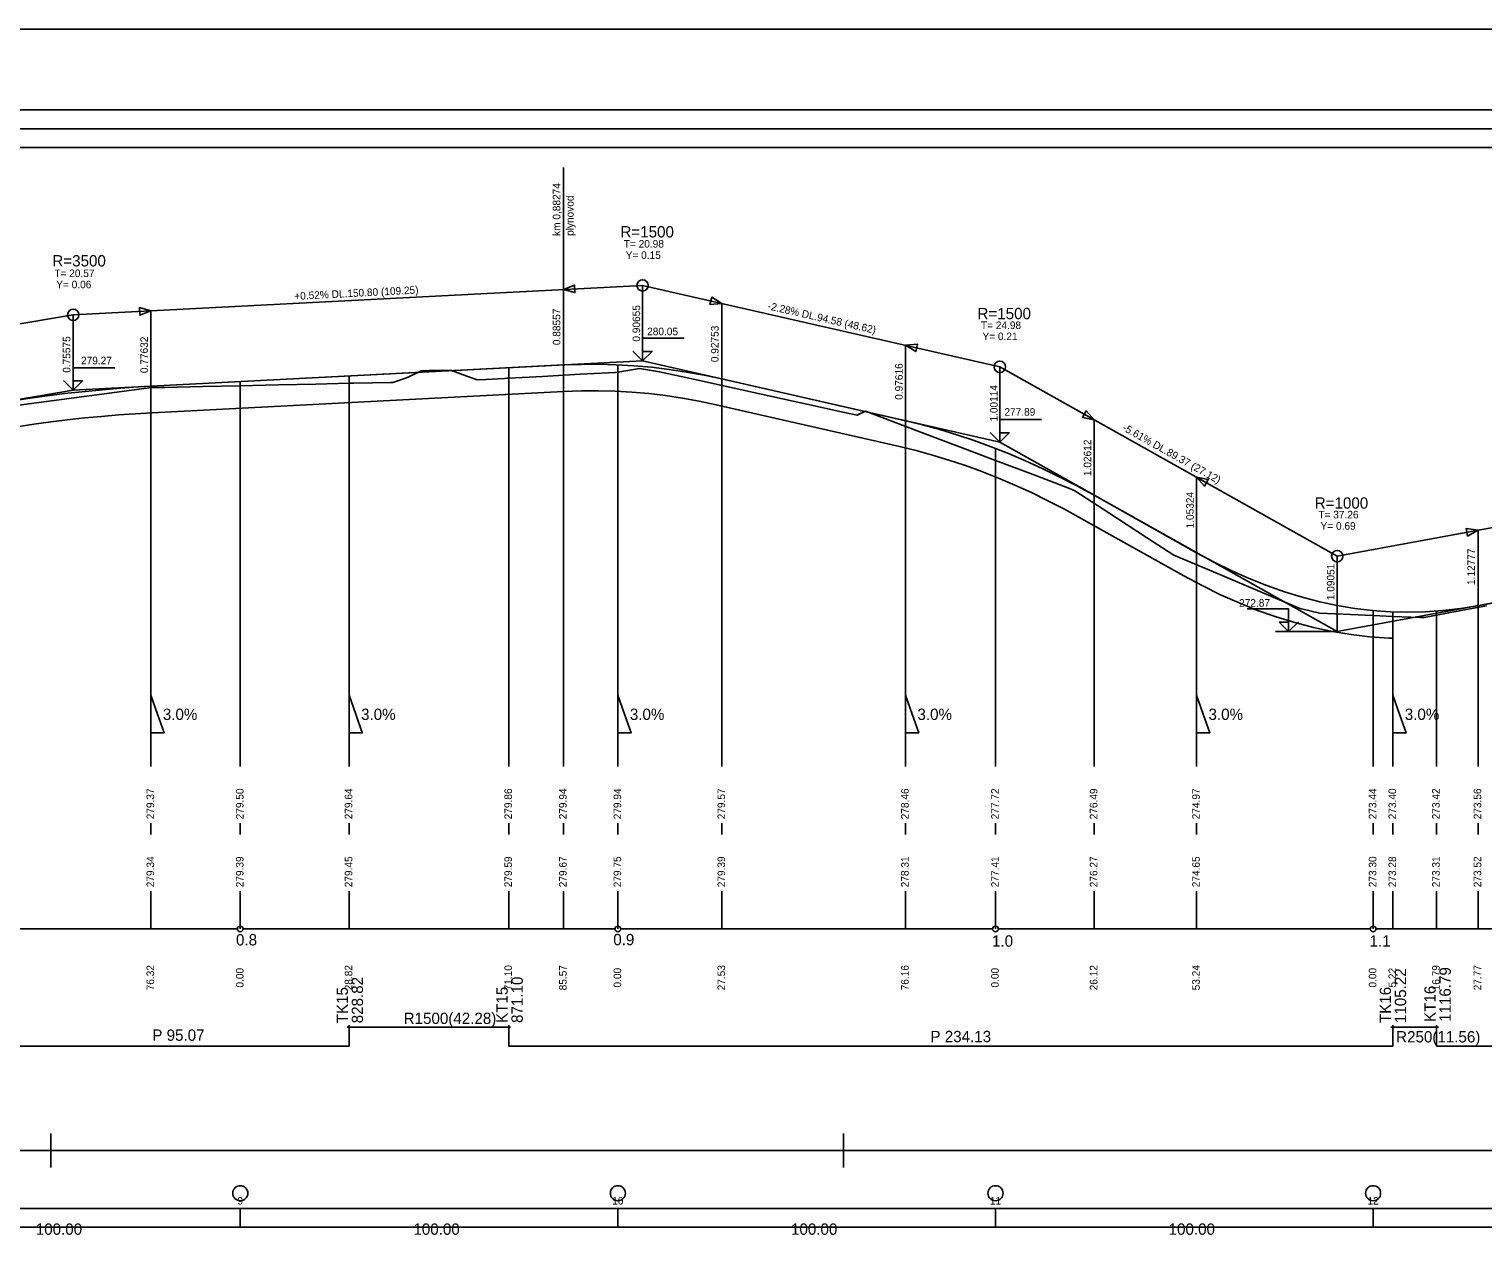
# Model space of a CAD drawing. Extents: x 1531 to 1699, y 61 to 93.
# Drawn here: x 1614.1 to 1652.6, y 60.9 to 92.84 of the extents above; entities that cross this region are included whole.
import ezdxf

# ---------------------------------------------------------------- set-up
doc = ezdxf.new("R2010")
doc.units = 0
for name, color, linetype in [('KOTA', 7, 'Continuous'), ('NOVY_STAV', 7, 'Continuous'), ('NS_OBLOUK', 7, 'Continuous'), ('REZY_PO', 7, 'Continuous'), ('SESTAVY_REZU_PO', 7, 'Continuous'), ('SKLONOVE_POMERY', 7, 'Continuous'), ('SMEROVE_POMERY', 7, 'Continuous'), ('SMEROVE_POMERY_KOD', 7, 'Continuous'), ('SVK_STAT', 7, 'Continuous'), ('TABULKY', 7, 'Continuous'), ('u_drenaz', 7, 'Continuous'), ('u_popis', 7, 'Continuous'), ('u_pricne_rezy', 7, 'Continuous'), ('x_formát_rám', 7, 'Continuous')]:
    doc.layers.add(name, color=color, linetype=linetype)

msp = doc.modelspace()

# ---------------------------------------------------------------- linework, layer by layer
at = {"layer": 'KOTA'}
msp.add_line((1648.745, 76.875), (1647.111, 76.875), dxfattribs=at)
for points in [[(1630.35, 84.047), (1630.1, 84.297), (1630.35, 84.047), (1630.35, 84.647), (1631.45, 84.647)], [(1630.35, 84.297), (1630.35, 84.047), (1630.6, 84.297), (1630.35, 84.297)], [(1630.35, 84.047), (1630.6, 84.297), (1630.35, 84.297)], [(1630.35, 84.047), (1630.35, 84.047)], [(1615.27, 83.267), (1615.02, 83.517), (1615.27, 83.267), (1615.27, 83.867), (1616.37, 83.867)], [(1615.27, 83.517), (1615.27, 83.267), (1615.52, 83.517), (1615.27, 83.517)], [(1615.27, 83.267), (1615.52, 83.517), (1615.27, 83.517)], [(1615.27, 83.267), (1615.27, 83.267)], [(1639.808, 81.89), (1639.558, 82.14), (1639.808, 81.89), (1639.808, 82.49), (1640.908, 82.49)], [(1639.808, 82.14), (1639.808, 81.89), (1640.058, 82.14), (1639.808, 82.14)], [(1639.808, 81.89), (1640.058, 82.14), (1639.808, 82.14)], [(1639.808, 81.89), (1639.808, 81.89)], [(1647.457, 76.875), (1647.707, 77.125), (1647.457, 76.875), (1647.457, 77.475), (1646.357, 77.475)], [(1647.457, 77.125), (1647.457, 76.875), (1647.207, 77.125), (1647.457, 77.125)], [(1647.457, 76.875), (1647.207, 77.125), (1647.457, 77.125)], [(1647.457, 76.875), (1647.457, 76.875)]]:
    msp.add_lwpolyline(points, dxfattribs=at)
at = {"layer": 'NOVY_STAV'}
for points in [[(1615.27, 85.267), (1630.35, 86.047)], [(1630.35, 84.047), (1630.35, 86.047)], [(1630.35, 86.047), (1639.808, 83.89)], [(1597.924, 82.331), (1615.27, 85.267)], [(1615.27, 83.267), (1615.27, 85.267)], [(1539.694, 84.06), (1549.705, 82.699), (1562.624, 80.344), (1572.147, 75.955), (1577.446, 75.638), (1581.466, 77.127), (1586.379, 77.333), (1597.924, 80.331), (1615.27, 83.267), (1630.35, 84.047), (1639.808, 81.89), (1648.745, 76.875), (1657.192, 78.43), (1660.774, 78.567), (1665.184, 79.201), (1673.611, 79.536), (1676.863, 81.654)], [(1613.67, 82.993), (1614.127, 83.061), (1614.584, 83.124), (1615.041, 83.18), (1615.498, 83.231), (1615.955, 83.275), (1616.412, 83.314), (1616.869, 83.347), (1617.326, 83.373), (1628.252, 83.938), (1628.718, 83.955), (1629.184, 83.957), (1629.65, 83.945), (1630.117, 83.919), (1630.583, 83.877), (1631.049, 83.822), (1631.515, 83.752), (1631.981, 83.667), (1632.448, 83.568), (1637.31, 82.459), (1637.764, 82.349), (1638.218, 82.225), (1638.673, 82.087), (1639.127, 81.935), (1639.581, 81.77), (1640.035, 81.59), (1640.489, 81.397), (1640.944, 81.191), (1641.398, 80.97), (1641.852, 80.736), (1642.306, 80.488), (1645.019, 78.966), (1645.484, 78.715), (1645.95, 78.487), (1646.416, 78.279), (1646.882, 78.094), (1647.348, 77.93), (1647.813, 77.788), (1648.279, 77.668), (1648.745, 77.569), (1649.211, 77.492), (1649.677, 77.437), (1650.142, 77.403), (1650.608, 77.392), (1651.074, 77.401), (1651.54, 77.433), (1652.006, 77.486), (1652.471, 77.561), (1656.608, 78.323)], [(1639.808, 81.89), (1639.808, 83.89)], [(1639.808, 83.89), (1648.745, 78.875)], [(1648.745, 78.875), (1657.192, 80.43)], [(1648.745, 76.875), (1648.745, 78.875)]]:
    msp.add_lwpolyline(points, dxfattribs=at)
for centre in [(1630.35, 86.047), (1615.27, 85.267), (1639.808, 83.89), (1648.745, 78.875)]:
    msp.add_circle(centre, 0.15, dxfattribs=at)
at = {"layer": 'NS_OBLOUK'}
for points in [[(1628.252, 85.938), (1628.556, 85.854), (1628.546, 86.053), (1628.252, 85.938)], [(1628.252, 83.938), (1628.252, 85.938)], [(1632.133, 85.537), (1632.448, 85.568), (1632.178, 85.732), (1632.133, 85.537)], [(1632.448, 83.568), (1632.448, 85.568)], [(1617.032, 85.258), (1617.326, 85.373), (1617.021, 85.458), (1617.032, 85.258)], [(1617.326, 83.373), (1617.326, 85.373)], [(1637.31, 84.459), (1637.58, 84.295), (1637.625, 84.49), (1637.31, 84.459)], [(1637.31, 82.459), (1637.31, 84.459)], [(1641.996, 82.548), (1642.306, 82.488), (1642.094, 82.722), (1641.996, 82.548)], [(1642.306, 80.488), (1642.306, 82.488)], [(1645.019, 78.966), (1645.019, 80.966)], [(1645.019, 80.966), (1645.231, 80.732), (1645.329, 80.906), (1645.019, 80.966)], [(1652.195, 79.408), (1652.472, 79.561), (1652.158, 79.605), (1652.195, 79.408)], [(1652.472, 77.561), (1652.472, 79.561)]]:
    msp.add_lwpolyline(points, dxfattribs=at)
for points in [[(1628.252, 85.938), (1628.546, 86.053), (1628.556, 85.854)], [(1632.448, 85.568), (1632.178, 85.732), (1632.133, 85.537)], [(1617.326, 85.373), (1617.021, 85.458), (1617.032, 85.258)], [(1637.31, 84.459), (1637.625, 84.49), (1637.58, 84.295)], [(1642.306, 82.488), (1642.094, 82.722), (1641.996, 82.548)], [(1645.019, 80.966), (1645.329, 80.906), (1645.231, 80.732)], [(1652.472, 79.561), (1652.158, 79.605), (1652.195, 79.408)]]:
    msp.add_lwpolyline(points, close=True, dxfattribs=at)
at = {"layer": 'REZY_PO'}
msp.add_lwpolyline([(1613.694, 82.856), (1614.694, 82.989), (1615.694, 83.123), (1616.694, 83.257), (1616.945, 83.29), (1617.352, 83.339), (1617.694, 83.346), (1618.694, 83.368), (1619.694, 83.39), (1619.694, 83.39), (1620.694, 83.412), (1621.694, 83.434), (1622.576, 83.453), (1622.635, 83.454), (1622.694, 83.455), (1623.194, 83.466), (1623.694, 83.477), (1623.732, 83.477), (1624.098, 83.6), (1624.194, 83.646), (1624.487, 83.787), (1624.694, 83.789), (1625.194, 83.792), (1625.284, 83.793), (1625.694, 83.644), (1625.969, 83.544), (1626.194, 83.556), (1626.694, 83.583), (1626.749, 83.586), (1626.804, 83.589), (1627.694, 83.637), (1628.694, 83.691), (1629.63, 83.741), (1629.694, 83.752), (1629.694, 83.752), (1630.265, 83.847), (1630.694, 83.775), (1630.793, 83.759), (1631.694, 83.56), (1632.694, 83.34), (1633.694, 83.12), (1634.694, 82.9), (1635.694, 82.68), (1636.027, 82.607), (1636.249, 82.714), (1636.694, 82.546), (1637.694, 82.168), (1638.694, 81.79), (1639.694, 81.412), (1639.694, 81.412), (1640.694, 81.034), (1641.496, 80.731), (1641.694, 80.645), (1641.793, 80.602), (1642.694, 80.018), (1643.694, 79.37), (1644.415, 78.903), (1644.694, 78.785), (1645.694, 78.363), (1646.694, 77.94), (1647.694, 77.518), (1647.766, 77.488), (1648.278, 77.362), (1648.694, 77.345), (1649.694, 77.302), (1649.694, 77.302), (1650.217, 77.28), (1650.456, 77.27), (1650.694, 77.259), (1650.948, 77.247), (1651.034, 77.247), (1651.046, 77.247), (1651.373, 77.31), (1651.373, 77.31), (1651.373, 77.31), (1651.694, 77.371), (1652.694, 77.563)], dxfattribs=at)
at = {"layer": 'SESTAVY_REZU_PO'}
for points in [[(1609.769, 69), (1619.619, 69)], [(1619.769, 69), (1629.619, 69)], [(1629.769, 69), (1639.619, 69)], [(1639.769, 69), (1649.619, 69)], [(1649.769, 69), (1659.619, 69)]]:
    msp.add_lwpolyline(points, dxfattribs=at)
for centre in [(1619.694, 69), (1629.694, 69), (1639.694, 69), (1649.694, 69)]:
    msp.add_circle(centre, 0.075, dxfattribs=at)
at = {"layer": 'SKLONOVE_POMERY'}
for points in [[(1617.326, 74.192), (1617.326, 75.192), (1617.326, 75.192), (1617.501, 74.692), (1617.676, 74.192), (1617.326, 74.192)], [(1622.576, 74.192), (1622.576, 75.192), (1622.576, 75.192), (1622.751, 74.692), (1622.926, 74.192), (1622.576, 74.192)], [(1629.694, 74.192), (1629.694, 75.192), (1629.694, 75.192), (1629.869, 74.692), (1630.044, 74.192), (1629.694, 74.192)], [(1637.31, 74.192), (1637.31, 75.192), (1637.31, 75.192), (1637.485, 74.692), (1637.66, 74.192), (1637.31, 74.192)], [(1645.019, 74.192), (1645.019, 75.192), (1645.019, 75.192), (1645.194, 74.692), (1645.369, 74.192), (1645.019, 74.192)], [(1650.217, 74.192), (1650.217, 75.192), (1650.217, 75.192), (1650.392, 74.692), (1650.567, 74.192), (1650.217, 74.192)]]:
    msp.add_lwpolyline(points, dxfattribs=at)
at = {"layer": 'SMEROVE_POMERY'}
msp.add_lwpolyline([(1613.069, 65.899), (1622.576, 65.899), (1622.576, 66.399), (1626.804, 66.399), (1626.804, 65.899), (1650.217, 65.899), (1650.217, 66.399), (1651.373, 66.399), (1651.373, 65.899), (1656.565, 65.899)], dxfattribs=at)
at = {"layer": 'SMEROVE_POMERY_KOD'}
for points in [[(1622.526, 66.399), (1622.626, 66.399)], [(1622.576, 66.349), (1622.576, 66.449)], [(1626.754, 66.399), (1626.854, 66.399)], [(1626.804, 66.349), (1626.804, 66.449)], [(1650.167, 66.399), (1650.267, 66.399)], [(1650.217, 66.349), (1650.217, 66.449)], [(1651.323, 66.399), (1651.423, 66.399)], [(1651.373, 66.349), (1651.373, 66.449)]]:
    msp.add_lwpolyline(points, dxfattribs=at)
at = {"layer": 'SVK_STAT'}
for points in [[(1628.252, 73.3), (1628.252, 83.938)], [(1629.694, 73.3), (1629.694, 83.943)], [(1622.576, 73.3), (1622.576, 83.645)], [(1626.804, 73.3), (1626.804, 83.863)], [(1632.448, 73.3), (1632.448, 83.568)], [(1617.326, 73.3), (1617.326, 83.373)], [(1619.694, 73.3), (1619.694, 83.496)], [(1637.31, 73.3), (1637.31, 82.459)], [(1639.694, 73.3), (1639.694, 81.725)], [(1642.306, 73.3), (1642.306, 80.488)], [(1645.019, 73.3), (1645.019, 78.966)], [(1649.694, 73.3), (1649.694, 77.436)], [(1650.217, 73.3), (1650.217, 77.402)], [(1651.373, 73.3), (1651.373, 77.422)], [(1652.472, 73.3), (1652.472, 77.561)], [(1617.326, 71.5), (1617.326, 71.8)], [(1619.694, 71.5), (1619.694, 71.8)], [(1622.576, 71.5), (1622.576, 71.8)], [(1626.804, 71.5), (1626.804, 71.8)], [(1628.252, 71.5), (1628.252, 71.8)], [(1629.694, 71.5), (1629.694, 71.8)], [(1632.448, 71.5), (1632.448, 71.8)], [(1637.31, 71.5), (1637.31, 71.8)], [(1639.694, 71.5), (1639.694, 71.8)], [(1642.306, 71.5), (1642.306, 71.8)], [(1645.019, 71.5), (1645.019, 71.8)], [(1649.694, 71.5), (1649.694, 71.8)], [(1650.217, 71.5), (1650.217, 71.8)], [(1651.373, 71.5), (1651.373, 71.8)], [(1652.472, 71.5), (1652.472, 71.8)], [(1617.326, 69), (1617.326, 70)], [(1619.694, 69), (1619.694, 70)], [(1622.576, 69), (1622.576, 70)], [(1626.804, 69), (1626.804, 70)], [(1628.252, 69), (1628.252, 70)], [(1629.694, 69), (1629.694, 70)], [(1632.448, 69), (1632.448, 70)], [(1637.31, 69), (1637.31, 70)], [(1639.694, 69), (1639.694, 70)], [(1642.306, 69), (1642.306, 70)], [(1645.019, 69), (1645.019, 70)], [(1649.694, 69), (1649.694, 70)], [(1650.217, 69), (1650.217, 70)], [(1651.373, 69), (1651.373, 70)], [(1652.472, 69), (1652.472, 70)]]:
    msp.add_lwpolyline(points, dxfattribs=at)
at = {"layer": 'TABULKY'}
for points in [[(1539.694, 89.697), (1676.863, 89.697), (1676.863, 90.697), (1539.694, 90.697), (1539.694, 89.697)], [(1539.694, 90.197), (1676.863, 90.197)]]:
    msp.add_lwpolyline(points, dxfattribs=at)
at = {"layer": 'u_drenaz'}
for points in [[(1613.778, 82.301), (1614.226, 82.369), (1614.674, 82.43), (1615.122, 82.485), (1615.57, 82.535), (1616.018, 82.578), (1616.466, 82.616), (1616.914, 82.648), (1617.365, 82.674), (1628.252, 83.237)], [(1628.252, 83.237), (1628.732, 83.255), (1629.177, 83.257), (1629.621, 83.246), (1630.066, 83.22), (1630.511, 83.181), (1630.956, 83.128), (1631.401, 83.061), (1631.846, 82.98), (1632.297, 82.885), (1637.149, 81.778), (1637.589, 81.671), (1638.024, 81.552), (1638.46, 81.42), (1638.896, 81.274), (1639.333, 81.115), (1639.77, 80.943), (1640.207, 80.757), (1640.646, 80.557), (1641.084, 80.344), (1641.524, 80.118), (1641.967, 79.876), (1644.682, 78.352), (1645.164, 78.093), (1645.654, 77.852), (1646.144, 77.634), (1646.636, 77.438), (1647.129, 77.265), (1647.624, 77.114), (1648.119, 76.986), (1648.615, 76.881), (1649.112, 76.799), (1649.61, 76.74), (1650.108, 76.704), (1650.217, 76.701)]]:
    msp.add_lwpolyline(points, dxfattribs=at)
at = {"layer": 'u_popis'}
msp.add_lwpolyline([(1628.252, 83.1), (1628.252, 89.17)], dxfattribs=at)
at = {"layer": 'u_pricne_rezy'}
for points in [[(1539.694, 61.1), (1676.863, 61.1), (1676.863, 61.6), (1539.694, 61.6), (1539.694, 61.1)], [(1619.694, 61.1), (1619.694, 61.6)], [(1629.694, 61.1), (1629.694, 61.6)], [(1639.694, 61.1), (1639.694, 61.6)], [(1649.694, 61.1), (1649.694, 61.6)]]:
    msp.add_lwpolyline(points, dxfattribs=at)
for centre in [(1619.694, 62), (1629.694, 62), (1639.694, 62), (1649.694, 62)]:
    msp.add_circle(centre, 0.2, dxfattribs=at)
at = {"layer": 'x_formát_rám'}
for p, q in [((1614.673, 63.586), (1614.673, 62.686)), ((1635.673, 63.586), (1635.673, 62.686))]:
    msp.add_line(p, q, dxfattribs=at)
msp.add_lwpolyline([(1530.673, 63.136), (1698.673, 63.136), (1698.673, 92.836), (1530.673, 92.836)], close=True, dxfattribs=at)

# ---------------------------------------------------------------- texts
at = {"layer": 'KOTA'}
for s, p in [('280.05', (1630.469, 84.726)), ('279.27', (1615.477, 83.956)), ('277.89', (1639.93, 82.594)), ('272.87', (1646.146, 77.536))]:
    msp.add_text(s, height=0.2, dxfattribs=at).set_placement(p)
at = {"layer": 'NOVY_STAV'}
for s, rotation, p in [('+0.52% DL.150.80 (109.25)', 2.9601, (1621.13, 85.661)), (' 0.90655', 90, (1630.283, 84.483)), ('-2.28% DL.94.58 (48.62)', 347.1542, (1633.649, 85.414)), (' 0.75575', 90, (1615.194, 83.657)), (' 1.00114', 90, (1639.751, 82.365)), ('-5.61% DL.89.37 (27.12)', 330.702, (1643.034, 82.22)), (' 1.09051', 90, (1648.67, 77.634))]:
    msp.add_text(s, height=0.2, rotation=rotation, dxfattribs=at).set_placement(p)
at = {"layer": 'NS_OBLOUK'}
for s, height, p in [('R=1500', 0.3, (1629.762, 87.316)), ('T= 20.98', 0.2, (1629.85, 87.047)), ('R=3500', 0.3, (1614.718, 86.548)), ('Y= 0.15', 0.2, (1629.901, 86.747)), ('T= 20.57', 0.2, (1614.77, 86.267)), ('Y= 0.06', 0.2, (1614.821, 85.97)), ('R=1500', 0.3, (1639.217, 85.15)), ('T= 24.98', 0.2, (1639.308, 84.89)), ('Y= 0.21', 0.2, (1639.35, 84.596)), ('R=1000', 0.3, (1648.148, 80.132)), ('T= 37.26', 0.2, (1648.245, 79.875)), ('Y= 0.69', 0.2, (1648.303, 79.575))]:
    msp.add_text(s, height=height, dxfattribs=at).set_placement(p)
for s, p in [(' 0.88557', (1628.171, 84.389)), (' 0.92753', (1632.36, 83.938)), (' 0.77632', (1617.248, 83.649)), (' 0.97616', (1637.236, 82.941)), (' 1.02612', (1642.231, 80.921)), (' 1.05324', (1644.944, 79.535)), (' 1.12777', (1652.39, 78.036))]:
    msp.add_text(s, height=0.2, rotation=90, dxfattribs=at).set_placement(p)
at = {"layer": 'SESTAVY_REZU_PO'}
for s, p in [('0.8', (1619.581, 68.563)), ('0.9', (1629.572, 68.569)), ('1.0', (1639.602, 68.532)), ('1.1', (1649.599, 68.532))]:
    msp.add_text(s, height=0.3, dxfattribs=at).set_placement(p)
at = {"layer": 'SKLONOVE_POMERY'}
for p in [(1617.643, 74.536), (1622.893, 74.536), (1630.011, 74.536), (1637.627, 74.536), (1645.335, 74.536), (1650.533, 74.536)]:
    msp.add_text('3.0%', height=0.3, dxfattribs=at).set_placement(p)
at = {"layer": 'SMEROVE_POMERY'}
for s, p in [('R1500(42.28)', (1624.021, 66.483)), ('P 95.07', (1617.365, 66.038)), ('P 234.13', (1637.972, 66.001)), ('R250(11.56)', (1650.304, 65.994))]:
    msp.add_text(s, height=0.3, dxfattribs=at).set_placement(p)
at = {"layer": 'SMEROVE_POMERY_KOD'}
for s, p in [('1105.22', (1650.568, 66.508)), ('1116.79', (1651.751, 66.538)), ('TK15', (1622.545, 66.502)), ('828.82', (1622.945, 66.502)), ('KT15', (1626.776, 66.511)), ('871.10', (1627.176, 66.511)), ('TK16', (1650.168, 66.508)), ('KT16', (1651.351, 66.538))]:
    msp.add_text(s, height=0.3, rotation=90, dxfattribs=at).set_placement(p)
at = {"layer": 'SVK_STAT'}
for s, p in [(' 279.37', (1617.412, 71.83)), (' 279.50', (1619.78, 71.83)), (' 279.64', (1622.661, 71.83)), (' 279.86', (1626.889, 71.83)), (' 279.94', (1628.337, 71.83)), (' 279.94', (1629.78, 71.83)), (' 279.57', (1632.533, 71.83)), (' 278.46', (1637.395, 71.83)), (' 277.72', (1639.78, 71.83)), (' 276.49', (1642.392, 71.83)), (' 274.97', (1645.104, 71.83)), (' 273.44', (1649.78, 71.83)), (' 273.40', (1650.302, 71.83)), (' 273.42', (1651.458, 71.83)), (' 273.56', (1652.557, 71.83)), (' 279.34', (1617.412, 70.03)), (' 279.39', (1619.78, 70.03)), (' 279.45', (1622.661, 70.03)), (' 279.59', (1626.889, 70.03)), (' 279.67', (1628.337, 70.03)), (' 279.75', (1629.78, 70.03)), (' 279.39', (1632.533, 70.03)), (' 278.31', (1637.395, 70.03)), (' 277.41', (1639.78, 70.03)), (' 276.27', (1642.392, 70.03)), (' 274.65', (1645.104, 70.03)), (' 273.30', (1649.78, 70.03)), (' 273.28', (1650.302, 70.03)), (' 273.31', (1651.458, 70.03)), (' 273.52', (1652.557, 70.03)), (' 76.32', (1617.412, 67.3)), ('  0.00', (1619.78, 67.3)), (' 28.82', (1622.661, 67.3)), (' 71.10', (1626.889, 67.3)), (' 85.57', (1628.337, 67.3)), ('  0.00', (1629.78, 67.3)), (' 27.53', (1632.533, 67.3)), (' 76.16', (1637.395, 67.3)), ('  0.00', (1639.78, 67.3)), (' 26.12', (1642.392, 67.3)), (' 53.24', (1645.104, 67.3)), ('  0.00', (1649.78, 67.3)), ('  5.22', (1650.302, 67.3)), (' 16.79', (1651.458, 67.3)), (' 27.77', (1652.557, 67.3))]:
    msp.add_text(s, height=0.2, rotation=90, dxfattribs=at).set_placement(p)
at = {"layer": 'u_popis'}
for s, p in [('km 0,88274', (1628.17, 87.357)), ('plynovod', (1628.52, 87.357))]:
    msp.add_text(s, height=0.2, rotation=90, dxfattribs=at).set_placement(p)
at = {"layer": 'u_pricne_rezy'}
for s, height, p in [('9', 0.2, (1619.619, 61.7)), ('10', 0.2, (1629.544, 61.7)), ('11', 0.2, (1639.544, 61.7)), ('12', 0.2, (1649.544, 61.7)), ('100.00', 0.3, (1614.279, 60.9)), ('100.00', 0.3, (1624.279, 60.9)), ('100.00', 0.3, (1634.279, 60.9)), ('100.00', 0.3, (1644.279, 60.9))]:
    msp.add_text(s, height=height, dxfattribs=at).set_placement(p)

doc.saveas('drawing.dxf')
